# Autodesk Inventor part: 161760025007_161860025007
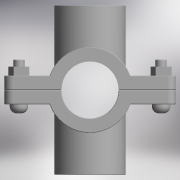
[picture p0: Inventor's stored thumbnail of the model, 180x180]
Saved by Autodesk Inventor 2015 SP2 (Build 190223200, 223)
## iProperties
Created: 2017-05
Part Number: 161760025007_161860025007
Material: Generic
Description: PLASSON DOUBLE SADDLE 25-3/4"
Document SubType Name: Modeling
Designer: KIM
Density: 1 g/cm^3
Appearance: Default
Author: KIM
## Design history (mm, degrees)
derived "16176.ipt"
feature "Solid1::16176.ipt"
feature "Solid2::16176.ipt"
tag "TaggingFeature1"
body "Solid1"
body "Solid2"
other parameters: "d0" = 37.5, "d1" = 75, "d2" = 12.5, "d3" = 25, "d5" = 0, "d6" = 3.75, "d7" = 75, "d8" = 0.1, "d10" = 0, "d11" = 0.25, "d20" = 0.25, "d23" = 0.25, "d36" = 8, "d37" = 6.4, "d38" = 20.5, "d39" = 0, "d40" = 3, "d41" = 4, "d42" = 0, "d43" = 5, "d44" = 3, "d45" = 0, "d46" = 0.25, "d52" = 24.117, "d53" = 19, "d54" = 0, "d55" = 15, "d57" = 0, "d58" = 27, "d60" = 0, "d62" = 8, "d63" = 25, "d66" = 0, "d67" = 74, "d68" = 31.3521, "d69" = 24.117, "d70" = 19, "d71" = 0, "d72" = 15, "d74" = 0, "d75" = 0.25, "d_" = 25, "B_" = 15, "G_" = 24.117, "A_" = 37, "L_" = 75, "l_2" = 19
